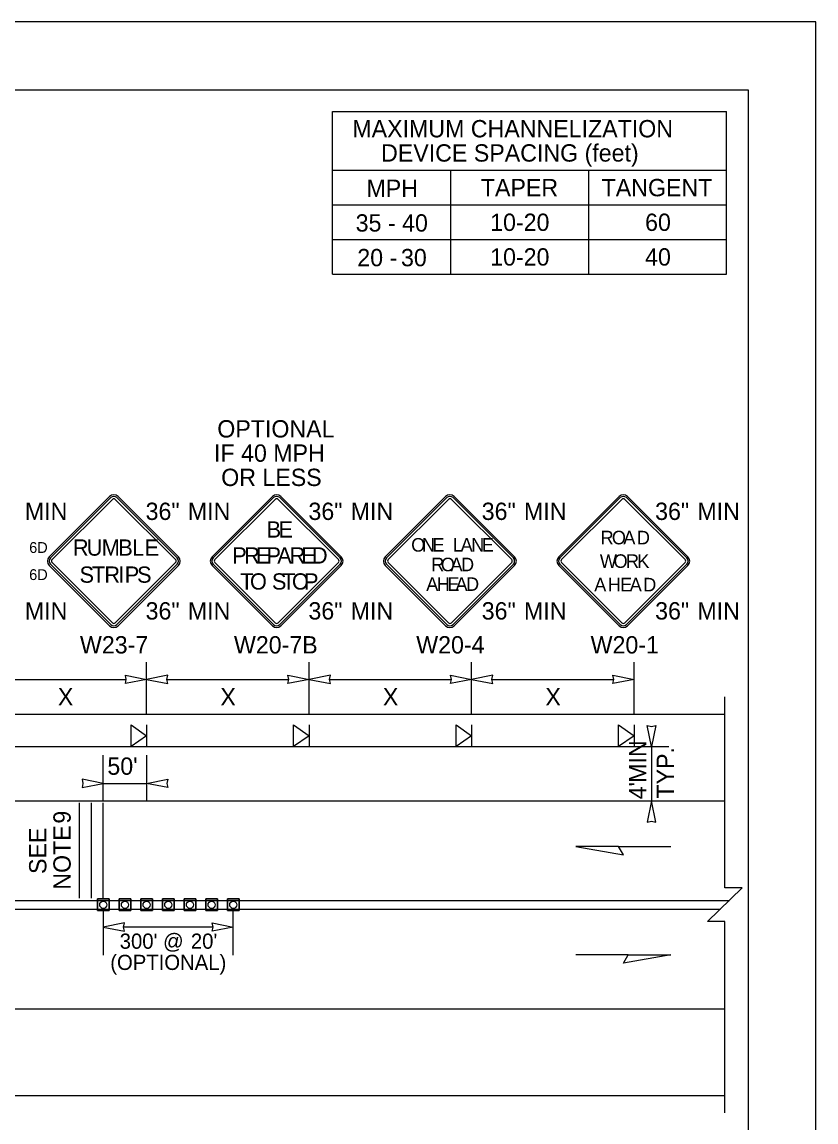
# Model space of a CAD drawing. Extents: x 99998.9 to 100095.7, y 99995 to 100010.7.
# Drawn here: x 100012.4 to 100016.06, y 100005.61 to 100010.69 of the extents above; entities that cross this region are included whole.
import ezdxf

# ---------------------------------------------------------------- set-up
doc = ezdxf.new("R2010")
doc.units = 0
for name, color, linetype in [('RD_ED_ShoulderPavedEdge', 7, 'Continuous'), ('RD_MK_LineDblYellowCenter', 7, 'Continuous'), ('RD_MK_LineEdgeWhite', 7, 'Continuous'), ('SH_GI_PlotLimits', 7, 'Continuous'), ('SH_GI_SheetBorder', 7, 'Continuous'), ('SH_TI_Tables', 7, 'Continuous'), ('TR_SN_ConstructionSigns', 7, 'Continuous'), ('TR_WZ_PortableSignMountBlk-Org', 7, 'Continuous'), ('TR_WZ_TrafficCone', 7, 'Continuous'), ('TR_WZ_WorkZoneDetails', 7, 'Continuous'), ('TR_WZ_WorkZoneTextCurrent', 7, 'Continuous')]:
    doc.layers.add(name, color=color, linetype=linetype)

msp = doc.modelspace()

# ---------------------------------------------------------------- linework, layer by layer
at = {"layer": 'RD_ED_ShoulderPavedEdge'}
for p, q in [((100000.1076, 100007.4923), (100015.6424, 100007.4923)), ((100000.1076, 100005.7323), (100015.6424, 100005.7323))]:
    msp.add_line(p, q, dxfattribs=at)
at = {"layer": 'RD_MK_LineDblYellowCenter'}
for p, q in [((100012.2733, 100006.6323), (100015.6631, 100006.6323)), ((100012.2733, 100006.5923), (100015.6218, 100006.5923))]:
    msp.add_line(p, q, dxfattribs=at)
at = {"layer": 'RD_MK_LineEdgeWhite'}
for p, q in [((100000.1076, 100007.0923), (100015.6424, 100007.0923)), ((100000.1076, 100006.1323), (100015.6424, 100006.1323))]:
    msp.add_line(p, q, dxfattribs=at)
at = {"layer": 'SH_GI_PlotLimits'}
msp.add_lwpolyline([(99999.0625, 99999.6875), (100016.0625, 99999.6875), (100016.0625, 100010.6875), (99999.0625, 100010.6875)], close=True, dxfattribs=at)
at = {"layer": 'SH_GI_SheetBorder'}
for p, q in [((100000, 100010.375), (100015.75, 100010.375)), ((100015.75, 100010.375), (100015.75, 100000))]:
    msp.add_line(p, q, dxfattribs=at)
at = {"layer": 'SH_TI_Tables'}
for p, q in [((100013.8318, 100010.275), (100015.65, 100010.275)), ((100013.8318, 100009.523), (100013.8318, 100010.275)), ((100015.65, 100009.523), (100015.65, 100010.275)), ((100013.8318, 100010.003), (100015.65, 100010.003)), ((100014.3773, 100009.523), (100014.3773, 100010.003)), ((100015.0136, 100009.523), (100015.0136, 100010.003)), ((100013.8318, 100009.843), (100014.3773, 100009.843)), ((100014.3773, 100009.843), (100015.0136, 100009.843)), ((100015.0136, 100009.843), (100015.65, 100009.843)), ((100013.8318, 100009.683), (100014.3773, 100009.683)), ((100014.3773, 100009.683), (100015.0136, 100009.683)), ((100015.0136, 100009.683), (100015.6472, 100009.683)), ((100013.8318, 100009.523), (100015.65, 100009.523))]:
    msp.add_line(p, q, dxfattribs=at)
at = {"layer": 'TR_SN_ConstructionSigns'}
for p, q in [((100012.8019, 100008.4972), (100012.5235, 100008.2188)), ((100012.8075, 100008.4917), (100012.529, 100008.2132)), ((100013.1146, 100008.2132), (100012.8362, 100008.4917)), ((100013.1201, 100008.2188), (100012.8417, 100008.4972)), ((100013.5535, 100008.4972), (100013.275, 100008.2188)), ((100013.559, 100008.4917), (100013.2806, 100008.2132)), ((100013.8661, 100008.2132), (100013.5877, 100008.4917)), ((100013.8717, 100008.2188), (100013.5932, 100008.4972)), ((100014.3532, 100008.4972), (100014.0747, 100008.2188)), ((100014.3587, 100008.4917), (100014.0803, 100008.2132)), ((100014.6658, 100008.2132), (100014.3874, 100008.4917)), ((100014.6714, 100008.2188), (100014.3929, 100008.4972)), ((100015.1535, 100008.4972), (100014.875, 100008.2188)), ((100015.159, 100008.4917), (100014.8806, 100008.2132)), ((100015.4661, 100008.2132), (100015.1877, 100008.4917)), ((100015.4717, 100008.2188), (100015.1932, 100008.4972)), ((100012.5368, 100008.2055), (100012.8152, 100008.4839)), ((100012.8285, 100008.4839), (100013.1069, 100008.2055)), ((100013.2883, 100008.2055), (100013.5667, 100008.4839)), ((100013.58, 100008.4839), (100013.8584, 100008.2055)), ((100014.088, 100008.2055), (100014.3664, 100008.4839)), ((100014.3797, 100008.4839), (100014.6581, 100008.2055)), ((100014.8883, 100008.2055), (100015.1667, 100008.4839)), ((100015.18, 100008.4839), (100015.4584, 100008.2055)), ((100012.529, 100008.1845), (100012.8075, 100007.9061)), ((100012.8152, 100007.9138), (100012.5368, 100008.1923)), ((100013.1069, 100008.1923), (100012.8285, 100007.9138)), ((100012.8362, 100007.9061), (100013.1146, 100008.1845)), ((100013.2806, 100008.1845), (100013.559, 100007.9061)), ((100013.5667, 100007.9138), (100013.2883, 100008.1923)), ((100013.8584, 100008.1923), (100013.58, 100007.9138)), ((100013.5877, 100007.9061), (100013.8661, 100008.1845)), ((100014.0803, 100008.1845), (100014.3587, 100007.9061)), ((100014.3664, 100007.9138), (100014.088, 100008.1923)), ((100014.6581, 100008.1923), (100014.3797, 100007.9138)), ((100014.3874, 100007.9061), (100014.6658, 100008.1845)), ((100014.8806, 100008.1845), (100015.159, 100007.9061)), ((100015.1667, 100007.9138), (100014.8883, 100008.1923)), ((100015.4584, 100008.1923), (100015.18, 100007.9138)), ((100015.1877, 100007.9061), (100015.4661, 100008.1845)), ((100012.5235, 100008.179), (100012.8019, 100007.9006)), ((100012.8417, 100007.9006), (100013.1201, 100008.179)), ((100013.275, 100008.179), (100013.5535, 100007.9006)), ((100013.5932, 100007.9006), (100013.8717, 100008.179)), ((100014.0747, 100008.179), (100014.3532, 100007.9006)), ((100014.3929, 100007.9006), (100014.6714, 100008.179)), ((100014.875, 100008.179), (100015.1535, 100007.9006)), ((100015.1932, 100007.9006), (100015.4717, 100008.179))]:
    msp.add_line(p, q, dxfattribs=at)
for centre, radius, start, end in [((100012.8218, 100008.4773), 0.0281, 45, 135), ((100012.8218, 100008.4773), 0.0203, 45, 135), ((100013.5733, 100008.4773), 0.0281, 45, 135), ((100013.5733, 100008.4773), 0.0203, 45, 135), ((100014.373, 100008.4773), 0.0281, 45, 135), ((100014.373, 100008.4773), 0.0203, 45, 135), ((100015.1733, 100008.4773), 0.0281, 45, 135), ((100015.1733, 100008.4773), 0.0203, 45, 135), ((100012.8218, 100008.4773), 0.00937, 45, 135), ((100013.5733, 100008.4773), 0.00937, 45, 135), ((100014.373, 100008.4773), 0.00937, 45, 135), ((100015.1733, 100008.4773), 0.00937, 45, 135), ((100012.5434, 100008.1989), 0.0281, 135, 225), ((100012.5434, 100008.1989), 0.0203, 135, 225), ((100012.5434, 100008.1989), 0.00937, 135, 225), ((100013.1003, 100008.1989), 0.00937, 315, 45), ((100013.1003, 100008.1989), 0.0203, 315, 45), ((100013.1003, 100008.1989), 0.0281, 315, 45), ((100013.2949, 100008.1989), 0.0281, 135, 225), ((100013.2949, 100008.1989), 0.0203, 135, 225), ((100013.2949, 100008.1989), 0.00937, 135, 225), ((100013.8518, 100008.1989), 0.00937, 315, 45), ((100013.8518, 100008.1989), 0.0203, 315, 45), ((100013.8518, 100008.1989), 0.0281, 315, 45), ((100014.0946, 100008.1989), 0.0281, 135, 225), ((100014.0946, 100008.1989), 0.0203, 135, 225), ((100014.0946, 100008.1989), 0.00937, 135, 225), ((100014.6515, 100008.1989), 0.00937, 315, 45), ((100014.6515, 100008.1989), 0.0203, 315, 45), ((100014.6515, 100008.1989), 0.0281, 315, 45), ((100014.8949, 100008.1989), 0.0281, 135, 225), ((100014.8949, 100008.1989), 0.0203, 135, 225), ((100014.8949, 100008.1989), 0.00937, 135, 225), ((100015.4518, 100008.1989), 0.00937, 315, 45), ((100015.4518, 100008.1989), 0.0203, 315, 45), ((100015.4518, 100008.1989), 0.0281, 315, 45), ((100012.8218, 100007.9205), 0.0281, 225, 315), ((100012.8218, 100007.9205), 0.0203, 225, 315), ((100012.8218, 100007.9205), 0.00937, 225, 315), ((100013.5733, 100007.9205), 0.0281, 225, 315), ((100013.5733, 100007.9205), 0.0203, 225, 315), ((100013.5733, 100007.9205), 0.00937, 225, 315), ((100014.373, 100007.9205), 0.0281, 225, 315), ((100014.373, 100007.9205), 0.0203, 225, 315), ((100014.373, 100007.9205), 0.00937, 225, 315), ((100015.1733, 100007.9205), 0.0281, 225, 315), ((100015.1733, 100007.9205), 0.0203, 225, 315), ((100015.1733, 100007.9205), 0.00937, 225, 315)]:
    msp.add_arc(centre, radius, start, end, dxfattribs=at)
at = {"layer": 'TR_WZ_PortableSignMountBlk-Org'}
for p, q in [((100012.9733, 100007.4422), (100012.9733, 100007.3422)), ((100013.7233, 100007.4422), (100013.7233, 100007.3422)), ((100014.4733, 100007.4422), (100014.4733, 100007.3422)), ((100015.2233, 100007.4422), (100015.2233, 100007.3422))]:
    msp.add_line(p, q, dxfattribs=at)
for points in [[(100012.9733, 100007.3923), (100012.9015, 100007.3422), (100012.9015, 100007.4422)], [(100013.7233, 100007.3923), (100013.6515, 100007.3422), (100013.6515, 100007.4422)], [(100014.4733, 100007.3923), (100014.4015, 100007.3422), (100014.4015, 100007.4422)], [(100015.2233, 100007.3923), (100015.1515, 100007.3422), (100015.1515, 100007.4422)]]:
    msp.add_lwpolyline(points, close=True, dxfattribs=at)
at = {"layer": 'TR_WZ_TrafficCone'}
for points in [[(100012.8, 100006.5857), (100012.7467, 100006.5857), (100012.7467, 100006.639), (100012.8, 100006.639), (100012.8, 100006.5857)], [(100012.8, 100006.639), (100012.7467, 100006.639), (100012.7467, 100006.5857), (100012.8, 100006.5857), (100012.8, 100006.639)], [(100012.9, 100006.5857), (100012.8467, 100006.5857), (100012.8467, 100006.639), (100012.9, 100006.639), (100012.9, 100006.5857)], [(100012.9, 100006.639), (100012.8467, 100006.639), (100012.8467, 100006.5857), (100012.9, 100006.5857), (100012.9, 100006.639)], [(100013, 100006.5857), (100012.9467, 100006.5857), (100012.9467, 100006.639), (100013, 100006.639), (100013, 100006.5857)], [(100013, 100006.639), (100012.9467, 100006.639), (100012.9467, 100006.5857), (100013, 100006.5857), (100013, 100006.639)], [(100013.1, 100006.5857), (100013.0467, 100006.5857), (100013.0467, 100006.639), (100013.1, 100006.639), (100013.1, 100006.5857)], [(100013.1, 100006.639), (100013.0467, 100006.639), (100013.0467, 100006.5857), (100013.1, 100006.5857), (100013.1, 100006.639)], [(100013.2, 100006.5857), (100013.1467, 100006.5857), (100013.1467, 100006.639), (100013.2, 100006.639), (100013.2, 100006.5857)], [(100013.2, 100006.639), (100013.1467, 100006.639), (100013.1467, 100006.5857), (100013.2, 100006.5857), (100013.2, 100006.639)], [(100013.3, 100006.5857), (100013.2467, 100006.5857), (100013.2467, 100006.639), (100013.3, 100006.639), (100013.3, 100006.5857)], [(100013.3, 100006.639), (100013.2467, 100006.639), (100013.2467, 100006.5857), (100013.3, 100006.5857), (100013.3, 100006.639)], [(100013.4, 100006.5857), (100013.3467, 100006.5857), (100013.3467, 100006.639), (100013.4, 100006.639), (100013.4, 100006.5857)], [(100013.4, 100006.639), (100013.3467, 100006.639), (100013.3467, 100006.5857), (100013.4, 100006.5857), (100013.4, 100006.639)]]:
    msp.add_lwpolyline(points, dxfattribs=at)
for centre in [(100012.7733, 100006.6123), (100012.8733, 100006.6123), (100012.9733, 100006.6123), (100013.0733, 100006.6123), (100013.1733, 100006.6123), (100013.2733, 100006.6123), (100013.3733, 100006.6123)]:
    msp.add_circle(centre, 0.0167, dxfattribs=at)
at = {"layer": 'TR_WZ_WorkZoneDetails'}
for p, q in [((100012.9733, 100007.4923), (100012.9733, 100007.7323)), ((100013.7233, 100007.4923), (100013.7233, 100007.7323)), ((100014.4733, 100007.4923), (100014.4733, 100007.7323)), ((100015.2233, 100007.4921), (100015.2233, 100007.7323)), ((100012.3171, 100007.6523), (100012.8796, 100007.6523)), ((100013.0671, 100007.6523), (100013.6296, 100007.6523)), ((100013.8171, 100007.6523), (100014.3796, 100007.6523)), ((100014.5671, 100007.6523), (100015.1296, 100007.6523)), ((100012.2233, 100007.3422), (100015.2233, 100007.3422)), ((100015.2233, 100007.3422), (100015.3833, 100007.3422)), ((100015.3033, 100007.3422), (100015.3033, 100007.0923)), ((100012.7733, 100007.0923), (100012.7733, 100007.3023)), ((100012.9733, 100007.3023), (100012.9733, 100007.0923)), ((100012.7733, 100007.1723), (100012.9733, 100007.1723)), ((100012.6628, 100006.6423), (100012.6628, 100007.0823)), ((100012.7185, 100006.6423), (100012.7185, 100007.0823)), ((100012.7733, 100006.6423), (100012.7733, 100007.0823)), ((100015.2233, 100007.0923), (100015.3833, 100007.0923)), ((100015.1513, 100006.8816), (100015.3924, 100006.8816)), ((100012.7733, 100006.589), (100012.7733, 100006.379)), ((100013.3733, 100006.379), (100013.3733, 100006.589)), ((100013.2796, 100006.509), (100012.8671, 100006.509)), ((100015.1959, 100006.3816), (100014.9548, 100006.3816))]:
    msp.add_line(p, q, dxfattribs=at)
for points in [[(100012.9733, 100007.6523), (100012.8751, 100007.6331), (100012.8796, 100007.6523), (100012.8751, 100007.6716)], [(100012.9733, 100007.6523), (100013.0716, 100007.6331), (100013.0671, 100007.6523), (100013.0716, 100007.6716)], [(100013.7233, 100007.6523), (100013.6251, 100007.6331), (100013.6296, 100007.6523), (100013.6251, 100007.6716)], [(100013.7233, 100007.6523), (100013.8216, 100007.6331), (100013.8171, 100007.6523), (100013.8216, 100007.6716)], [(100014.4733, 100007.6523), (100014.3751, 100007.6331), (100014.3796, 100007.6523), (100014.3751, 100007.6716)], [(100014.4733, 100007.6523), (100014.5716, 100007.6331), (100014.5671, 100007.6523), (100014.5716, 100007.6716)], [(100015.2233, 100007.6523), (100015.1251, 100007.6331), (100015.1296, 100007.6523), (100015.1251, 100007.6716)], [(100015.3033, 100007.3422), (100015.2841, 100007.4405), (100015.3033, 100007.436), (100015.3226, 100007.4405)], [(100012.7733, 100007.1723), (100012.6751, 100007.1916), (100012.6796, 100007.1723), (100012.6751, 100007.1531)], [(100012.9733, 100007.1723), (100013.0716, 100007.1916), (100013.0671, 100007.1723), (100013.0716, 100007.1531)], [(100015.3033, 100007.0923), (100015.2841, 100006.9941), (100015.3033, 100006.9986), (100015.3226, 100006.9941)], [(100014.9548, 100006.8816), (100015.1736, 100006.843), (100015.1513, 100006.8816)], [(100012.7733, 100006.509), (100012.8716, 100006.4897), (100012.8671, 100006.509), (100012.8716, 100006.5283)], [(100013.3733, 100006.509), (100013.2751, 100006.4897), (100013.2796, 100006.509), (100013.2751, 100006.5283)], [(100015.3924, 100006.3816), (100015.1736, 100006.343), (100015.1959, 100006.3816)]]:
    msp.add_lwpolyline(points, close=True, dxfattribs=at)
msp.add_lwpolyline([(100015.6424, 100005.6523), (100015.6424, 100006.5349), (100015.5624, 100006.5349), (100015.7225, 100006.6898), (100015.6424, 100006.6898), (100015.6424, 100007.5723)], dxfattribs=at)

# ---------------------------------------------------------------- texts
at = {"layer": 'SH_TI_Tables'}
for s, p in [('MAXIMUM CHANNELIZATION', (100013.9227, 100010.155)), ('DEVICE SPACING (feet)', (100014.0553, 100010.043)), ('TAPER', (100014.5157, 100009.883)), ('TANGENT', (100015.0731, 100009.883)), ('MPH', (100013.9878, 100009.8799)), ('35', (100013.9381, 100009.7199)), ('- 40', (100014.0869, 100009.7199)), ('10-20', (100014.5588, 100009.723)), ('60', (100015.2737, 100009.723)), ('20', (100013.9456, 100009.5599)), ('30', (100014.1472, 100009.5599)), ('10-20', (100014.5588, 100009.563)), ('40', (100015.2737, 100009.563)), ('-', (100014.0944, 100009.5599))]:
    msp.add_text(s, height=0.08, dxfattribs=at).set_placement(p)
at = {"layer": 'TR_SN_ConstructionSigns'}
for s, height, p in [('OPTIONAL', 0.08, (100013.2994, 100008.7694)), ('IF 40 MPH', 0.08, (100013.2843, 100008.6574)), ('OR LESS', 0.08, (100013.3175, 100008.5454)), ('B', 0.075, (100013.5271, 100008.3074)), ('E', 0.075, (100013.5814, 100008.3074)), ('R', 0.0625, (100015.0683, 100008.2762)), ('O', 0.0625, (100015.1204, 100008.2762)), ('A', 0.0625, (100015.1732, 100008.2762)), ('D', 0.0625, (100015.2359, 100008.2762)), ('6D', 0.05, (100012.4313, 100008.2364)), ('R', 0.075, (100012.6332, 100008.2239)), ('U', 0.075, (100012.697, 100008.2239)), ('M', 0.075, (100012.766, 100008.2239)), ('B', 0.075, (100012.8425, 100008.2239)), ('L', 0.075, (100012.9062, 100008.2239)), ('E', 0.075, (100012.964, 100008.2239)), ('O', 0.0625, (100014.1943, 100008.2426)), ('N', 0.0625, (100014.2437, 100008.2426)), ('E', 0.0625, (100014.2924, 100008.2426)), ('L', 0.0625, (100014.3868, 100008.2426)), ('A', 0.0625, (100014.4224, 100008.2426)), ('N', 0.0625, (100014.4712, 100008.2426)), ('E', 0.0625, (100014.5199, 100008.2426)), ('P', 0.075, (100013.3684, 100008.1874)), ('R', 0.075, (100013.4237, 100008.1874)), ('E', 0.075, (100013.4769, 100008.1874)), ('P', 0.075, (100013.5264, 100008.1874)), ('A', 0.075, (100013.5763, 100008.1874)), ('R', 0.075, (100013.6335, 100008.1874)), ('E', 0.075, (100013.6868, 100008.1874)), ('D', 0.075, (100013.7362, 100008.1874)), ('R', 0.0625, (100014.2868, 100008.152)), ('O', 0.0625, (100014.3312, 100008.152)), ('A', 0.0625, (100014.3755, 100008.152)), ('D', 0.0625, (100014.4243, 100008.152)), ('W', 0.0625, (100015.065, 100008.1676)), ('O', 0.0625, (100015.1282, 100008.1676)), ('R', 0.0625, (100015.1855, 100008.1676)), ('K', 0.0625, (100015.2379, 100008.1676)), ('6D', 0.05, (100012.4313, 100008.1114)), ('S', 0.075, (100012.6636, 100008.0989)), ('T', 0.075, (100012.7206, 100008.0989)), ('R', 0.075, (100012.7783, 100008.0989)), ('I', 0.075, (100012.8421, 100008.0989)), ('P', 0.075, (100012.8721, 100008.0989)), ('S', 0.075, (100012.9291, 100008.0989)), ('T', 0.075, (100013.4051, 100008.0674)), ('O', 0.075, (100013.4502, 100008.0674)), ('S', 0.075, (100013.5516, 100008.0674)), ('T', 0.075, (100013.5988, 100008.0674)), ('O', 0.075, (100013.6439, 100008.0674)), ('P', 0.075, (100013.6996, 100008.0674)), ('A', 0.0625, (100014.2637, 100008.0614)), ('H', 0.0625, (100014.3124, 100008.0614)), ('E', 0.0625, (100014.3612, 100008.0614)), ('A', 0.0625, (100014.3987, 100008.0614)), ('D', 0.0625, (100014.4474, 100008.0614)), ('A', 0.0625, (100015.039, 100008.0591)), ('H', 0.0625, (100015.1015, 100008.0591)), ('E', 0.0625, (100015.159, 100008.0591)), ('A', 0.0625, (100015.2027, 100008.0591)), ('D', 0.0625, (100015.2652, 100008.0591))]:
    msp.add_text(s, height=height, dxfattribs=at).set_placement(p)
for s, p in [('MIN', (100012.4114, 100008.3887)), ('36"', (100012.9686, 100008.3887)), ('MIN', (100013.1636, 100008.3887)), ('36"', (100013.7201, 100008.3887)), ('MIN', (100013.9151, 100008.3887)), ('36"', (100014.5198, 100008.3887)), ('MIN', (100014.7148, 100008.3887)), ('36"', (100015.3201, 100008.3887)), ('MIN', (100015.5151, 100008.3887)), ('MIN', (100012.4114, 100007.9291)), ('36"', (100012.9686, 100007.9291)), ('MIN', (100013.1636, 100007.9291)), ('36"', (100013.7201, 100007.9291)), ('MIN', (100013.9151, 100007.9291)), ('36"', (100014.5198, 100007.9291)), ('MIN', (100014.7148, 100007.9291)), ('36"', (100015.3201, 100007.9291)), ('MIN', (100015.5151, 100007.9291)), ('W23-7', (100012.6656, 100007.7723)), ('W20-7B', (100013.3763, 100007.7723)), ('W20-4', (100014.2176, 100007.7723)), ('W20-1', (100015.0224, 100007.7723))]:
    msp.add_text(s, height=0.08, rotation=360, dxfattribs=at).set_placement(p)
at = {"layer": 'TR_WZ_WorkZoneDetails'}
for s, p in [('9', (100012.6228, 100006.9868)), ('NOTE', (100012.6228, 100006.6819)), ('SEE', (100012.5108, 100006.7544))]:
    msp.add_text(s, height=0.08, rotation=90, dxfattribs=at).set_placement(p)
at = {"layer": 'TR_WZ_WorkZoneTextCurrent'}
for s, height, p in [('X', 0.08, (100012.5636, 100007.5323)), ('X', 0.08, (100013.3136, 100007.5323)), ('X', 0.08, (100014.0636, 100007.5323)), ('X', 0.08, (100014.8136, 100007.5323)), ("50'", 0.08, (100012.7921, 100007.2123)), ("300' @", 0.07, (100012.8491, 100006.4093)), ("20'", 0.07, (100013.1775, 100006.4093)), ('(OPTIONAL)', 0.07, (100012.8053, 100006.3113))]:
    msp.add_text(s, height=height, dxfattribs=at).set_placement(p)
for s, p in [('MIN', (100015.2793, 100007.1754)), ('TYP.', (100015.4073, 100007.1026)), ("4'", (100015.2793, 100007.0989))]:
    msp.add_text(s, height=0.08, rotation=90, dxfattribs=at).set_placement(p)

doc.saveas('drawing.dxf')
